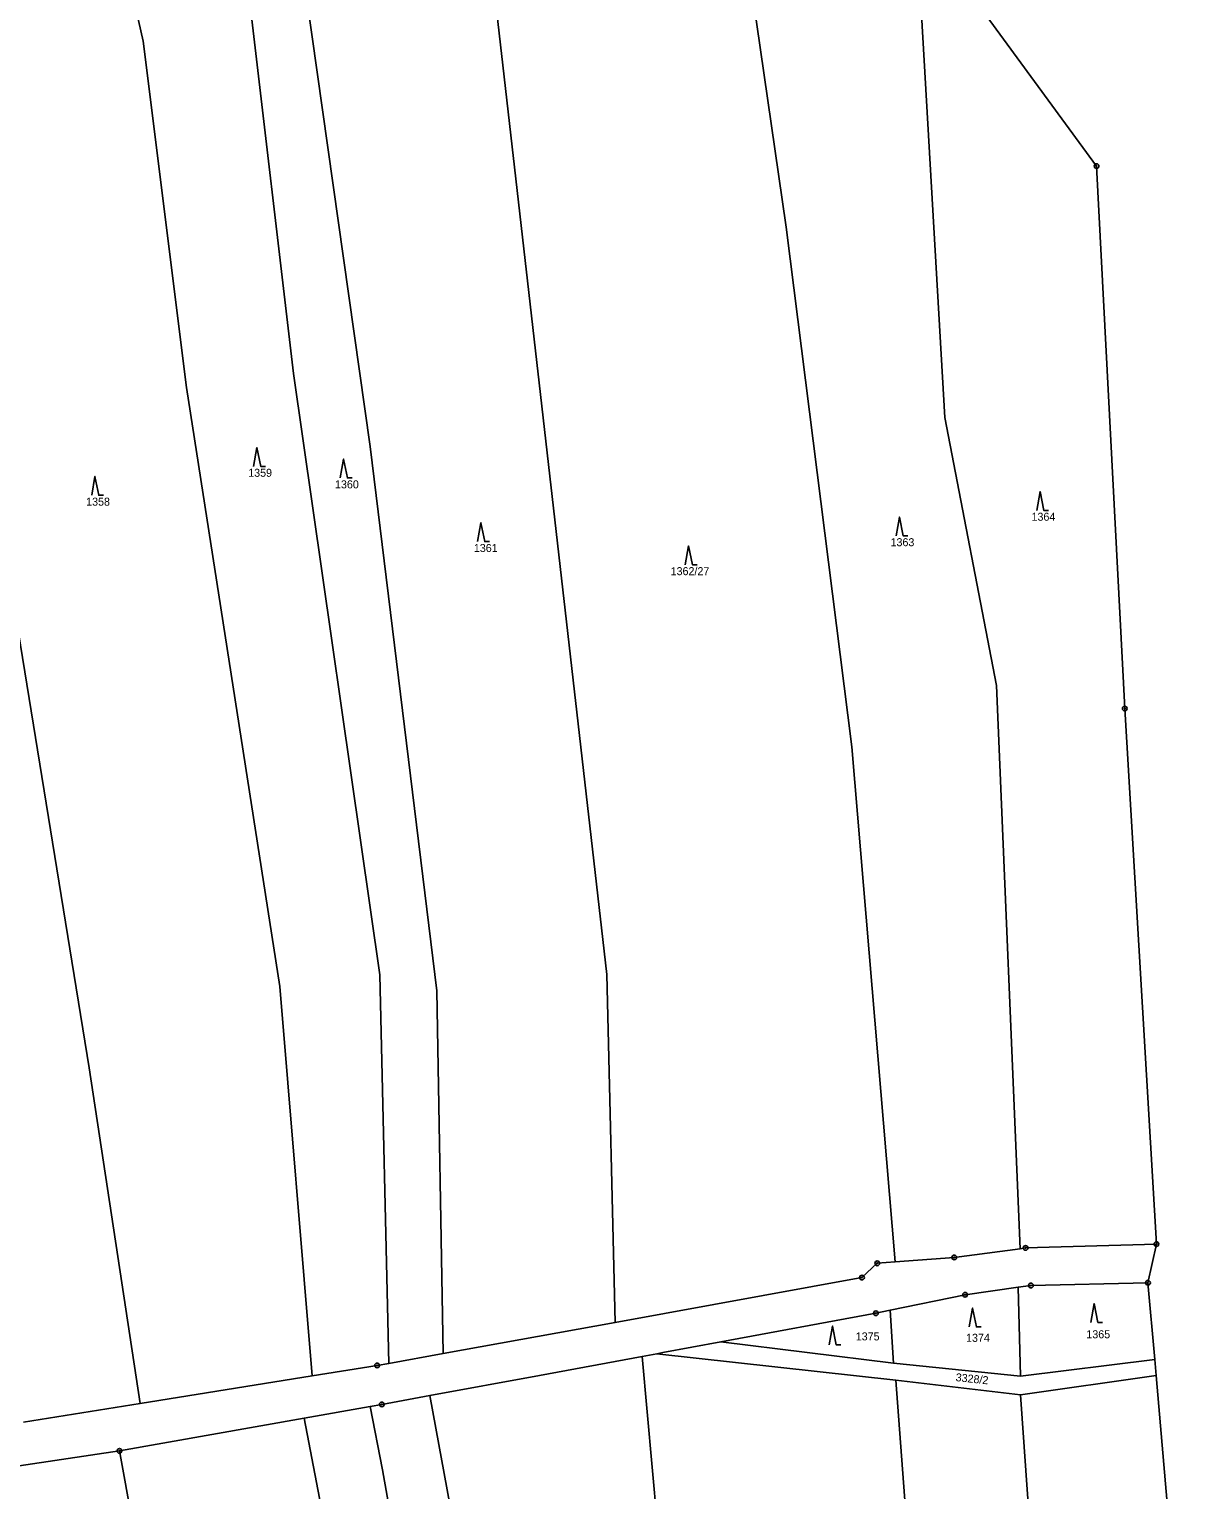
# Model space of a CAD drawing. Extents: x -763205 to -760228, y -1155311 to -1152844.
# Drawn here: x -760514.7 to -760268.7, y -1154798.5 to -1154488.2 of the extents above; entities that cross this region are included whole.
import ezdxf

# ---------------------------------------------------------------- set-up
doc = ezdxf.new("R2010")
doc.units = 0
for name, color, linetype in [('Vrstva 1', 7, 'Continuous'), ('Vrstva 13', 7, 'Continuous'), ('Vrstva 18', 7, 'Continuous'), ('Vrstva 24', 7, 'Continuous'), ('Vrstva 25', 7, 'Continuous'), ('Vrstva 6', 7, 'Continuous')]:
    doc.layers.add(name, color=color, linetype=linetype)

msp = doc.modelspace()

# ---------------------------------------------------------------- linework, layer by layer
at = {"layer": 'Vrstva 1'}
for p, q in [((-760318.32, -1154749.11), (-760304.35, -1154747.26)), ((-760304.35, -1154747.26), (-760303.16, -1154747.1)), ((-760303.16, -1154747.1), (-760275.4, -1154746.28)), ((-760337.91, -1154753.39), (-760334.66, -1154750.36)), ((-760334.66, -1154750.36), (-760330.84, -1154750.07)), ((-760330.84, -1154750.07), (-760318.32, -1154749.11)), ((-760390.34, -1154762.9), (-760337.91, -1154753.39)), ((-760316.03, -1154757.03), (-760304.78, -1154755.45)), ((-760304.78, -1154755.45), (-760302.05, -1154755.07)), ((-760302.05, -1154755.07), (-760277.19, -1154754.49)), ((-760331.92, -1154760.34), (-760316.03, -1154757.03)), ((-760426.8, -1154769.51), (-760390.34, -1154762.9)), ((-760367.91, -1154767.06), (-760334.96, -1154760.97)), ((-760334.96, -1154760.97), (-760331.92, -1154760.34)), ((-760380.16, -1154769.33), (-760367.91, -1154767.06)), ((-760454.63, -1154774.27), (-760440.86, -1154772.06)), ((-760440.86, -1154772.06), (-760438.36, -1154771.61)), ((-760438.36, -1154771.61), (-760426.8, -1154769.51)), ((-760406.38, -1154774.17), (-760384.56, -1154770.14)), ((-760384.56, -1154770.14), (-760381.44, -1154769.57)), ((-760381.44, -1154769.57), (-760380.16, -1154769.33)), ((-760491.19, -1154780.15), (-760454.63, -1154774.27)), ((-760429.64, -1154778.46), (-760406.38, -1154774.17)), ((-760515.9, -1154784.12), (-760491.19, -1154780.15)), ((-760456.33, -1154783.25), (-760442.32, -1154780.77)), ((-760442.32, -1154780.77), (-760439.86, -1154780.34)), ((-760439.86, -1154780.34), (-760429.64, -1154778.46)), ((-760495.56, -1154790.19), (-760456.33, -1154783.25)), ((-760522.11, -1154794.14), (-760495.56, -1154790.19)), ((-760495.56, -1154790.19), (-760486.7, -1154838.62))]:
    msp.add_line(p, q, dxfattribs=at)
at = {"layer": 'Vrstva 13'}
for p, q in [((-760320.78, -1154472.71), (-760288.09, -1154517.32)), ((-760288.09, -1154517.32), (-760282.13, -1154632.52)), ((-760282.13, -1154632.52), (-760275.4, -1154746.28)), ((-760275.4, -1154746.28), (-760277.19, -1154754.49)), ((-760277.19, -1154754.49), (-760275.76, -1154770.8)), ((-760275.76, -1154770.8), (-760275.47, -1154774.16)), ((-760275.47, -1154774.16), (-760268.74, -1154851.07))]:
    msp.add_line(p, q, dxfattribs=at)
at = {"layer": 'Vrstva 24'}
for centre, radius in [((-760288.09, -1154517.32), 0.5), ((-760288.09, -1154517.32), 0.1), ((-760282.13, -1154632.52), 0.5), ((-760282.13, -1154632.52), 0.1), ((-760303.16, -1154747.1), 0.5), ((-760303.16, -1154747.1), 0.1), ((-760275.4, -1154746.28), 0.5), ((-760275.4, -1154746.28), 0.1), ((-760334.66, -1154750.36), 0.5), ((-760334.66, -1154750.36), 0.1), ((-760318.32, -1154749.11), 0.5), ((-760318.32, -1154749.11), 0.1), ((-760337.91, -1154753.39), 0.5), ((-760337.91, -1154753.39), 0.1), ((-760316.03, -1154757.03), 0.5), ((-760302.05, -1154755.07), 0.5), ((-760302.05, -1154755.07), 0.1), ((-760277.19, -1154754.49), 0.5), ((-760277.19, -1154754.49), 0.1), ((-760316.03, -1154757.03), 0.1), ((-760334.96, -1154760.97), 0.5), ((-760334.96, -1154760.97), 0.1), ((-760440.86, -1154772.06), 0.5), ((-760440.86, -1154772.06), 0.1), ((-760439.86, -1154780.34), 0.5), ((-760439.86, -1154780.34), 0.1), ((-760495.56, -1154790.19), 0.5), ((-760495.56, -1154790.19), 0.1)]:
    msp.add_circle(centre, radius, dxfattribs=at)
at = {"layer": 'Vrstva 25'}
for points in [[(-760467.08, -1154581.1), (-760466.38, -1154577.1), (-760465.58, -1154581.1), (-760464.58, -1154581.1)], [(-760448.67, -1154583.56), (-760447.97, -1154579.56), (-760447.17, -1154583.56), (-760446.17, -1154583.56)], [(-760501.46, -1154587.24), (-760500.76, -1154583.24), (-760499.96, -1154587.24), (-760498.96, -1154587.24)], [(-760300.81, -1154590.44), (-760300.11, -1154586.44), (-760299.31, -1154590.44), (-760298.31, -1154590.44)], [(-760330.66, -1154595.85), (-760329.96, -1154591.85), (-760329.16, -1154595.85), (-760328.16, -1154595.85)], [(-760419.52, -1154597.08), (-760418.82, -1154593.08), (-760418.02, -1154597.08), (-760417.02, -1154597.08)], [(-760375.42, -1154602), (-760374.72, -1154598), (-760373.92, -1154602), (-760372.92, -1154602)], [(-760289.32, -1154762.92), (-760288.62, -1154758.92), (-760287.82, -1154762.92), (-760286.82, -1154762.92)], [(-760315.12, -1154763.86), (-760314.42, -1154759.86), (-760313.62, -1154763.86), (-760312.62, -1154763.86)], [(-760344.87, -1154767.69), (-760344.17, -1154763.69), (-760343.37, -1154767.69), (-760342.37, -1154767.69)]]:
    msp.add_lwpolyline(points, dxfattribs=at)
at = {"layer": 'Vrstva 6'}
for p, q in [((-760513.54, -1154389.56), (-760490.5, -1154490.75)), ((-760367.2, -1154438.93), (-760353.98, -1154530.31)), ((-760326.2, -1154468.47), (-760320.34, -1154570.69)), ((-760456.61, -1154475.84), (-760442.33, -1154576.88)), ((-760468.23, -1154479.37), (-760458.62, -1154561.34)), ((-760415.78, -1154481.59), (-760392.06, -1154688.99)), ((-760490.5, -1154490.75), (-760481.36, -1154564.32)), ((-760534.39, -1154509.56), (-760502.02, -1154708.86)), ((-760353.98, -1154530.31), (-760340.04, -1154640.67)), ((-760481.36, -1154564.32), (-760461.48, -1154691.57)), ((-760458.62, -1154561.34), (-760440.28, -1154689.11)), ((-760320.34, -1154570.69), (-760309.34, -1154627.65)), ((-760442.33, -1154576.88), (-760428.17, -1154692.45)), ((-760309.34, -1154627.65), (-760304.35, -1154747.26)), ((-760340.04, -1154640.67), (-760330.84, -1154750.07)), ((-760461.48, -1154691.57), (-760454.63, -1154774.27)), ((-760440.28, -1154689.11), (-760438.36, -1154771.61)), ((-760392.06, -1154688.99), (-760390.34, -1154762.9)), ((-760428.17, -1154692.45), (-760426.8, -1154769.51)), ((-760502.02, -1154708.86), (-760491.19, -1154780.15)), ((-760304.78, -1154755.45), (-760304.23, -1154774.3)), ((-760331.92, -1154760.34), (-760331.21, -1154771.55)), ((-760367.91, -1154767.06), (-760331.21, -1154771.55)), ((-760384.56, -1154770.14), (-760375.14, -1154875.03)), ((-760381.44, -1154769.57), (-760330.72, -1154775.17)), ((-760331.21, -1154771.55), (-760304.23, -1154774.3)), ((-760304.23, -1154774.3), (-760275.76, -1154770.8)), ((-760330.72, -1154775.17), (-760304.23, -1154778.3)), ((-760330.72, -1154775.17), (-760326.22, -1154834.86)), ((-760304.23, -1154778.3), (-760275.47, -1154774.16)), ((-760304.23, -1154778.3), (-760301.98, -1154810.29)), ((-760442.32, -1154780.77), (-760439.74, -1154794.19)), ((-760429.64, -1154778.46), (-760420.89, -1154826.34)), ((-760456.33, -1154783.25), (-760447.29, -1154830.14)), ((-760439.74, -1154794.19), (-760433.83, -1154827.36))]:
    msp.add_line(p, q, dxfattribs=at)

# ---------------------------------------------------------------- texts
at = {"layer": 'Vrstva 18'}
for s, p in [('1359', (-760468.227, -1154583.3)), ('1360', (-760449.797, -1154585.76)), ('1358', (-760502.637, -1154589.44)), ('1364', (-760301.917, -1154592.64)), ('1361', (-760420.317, -1154599.28)), ('1363', (-760331.847, -1154598.05)), ('1362/27', (-760378.537, -1154604.2)), ('1375', (-760339.237, -1154766.73)), ('1374', (-760315.817, -1154767.03)), ('1365', (-760290.277, -1154766.28))]:
    msp.add_text(s, height=1.7, dxfattribs=at).set_placement(p)
msp.add_text('3328/2', height=1.7, rotation=354.20251, dxfattribs=at).set_placement((-760318.084, -1154775.374))

doc.saveas('drawing.dxf')
